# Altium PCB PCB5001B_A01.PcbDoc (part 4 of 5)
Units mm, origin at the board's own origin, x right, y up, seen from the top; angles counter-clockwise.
Board outline 115 x 60 mm, 6 copper layers (Top Layer, GND Layer 2, Signal Layer 3, Signal Layer 4, VCC Layer 5, Bottom Layer), stack 1.555 mm thick; 370 components, 274 nets, 1305 pads, 1129 vias.
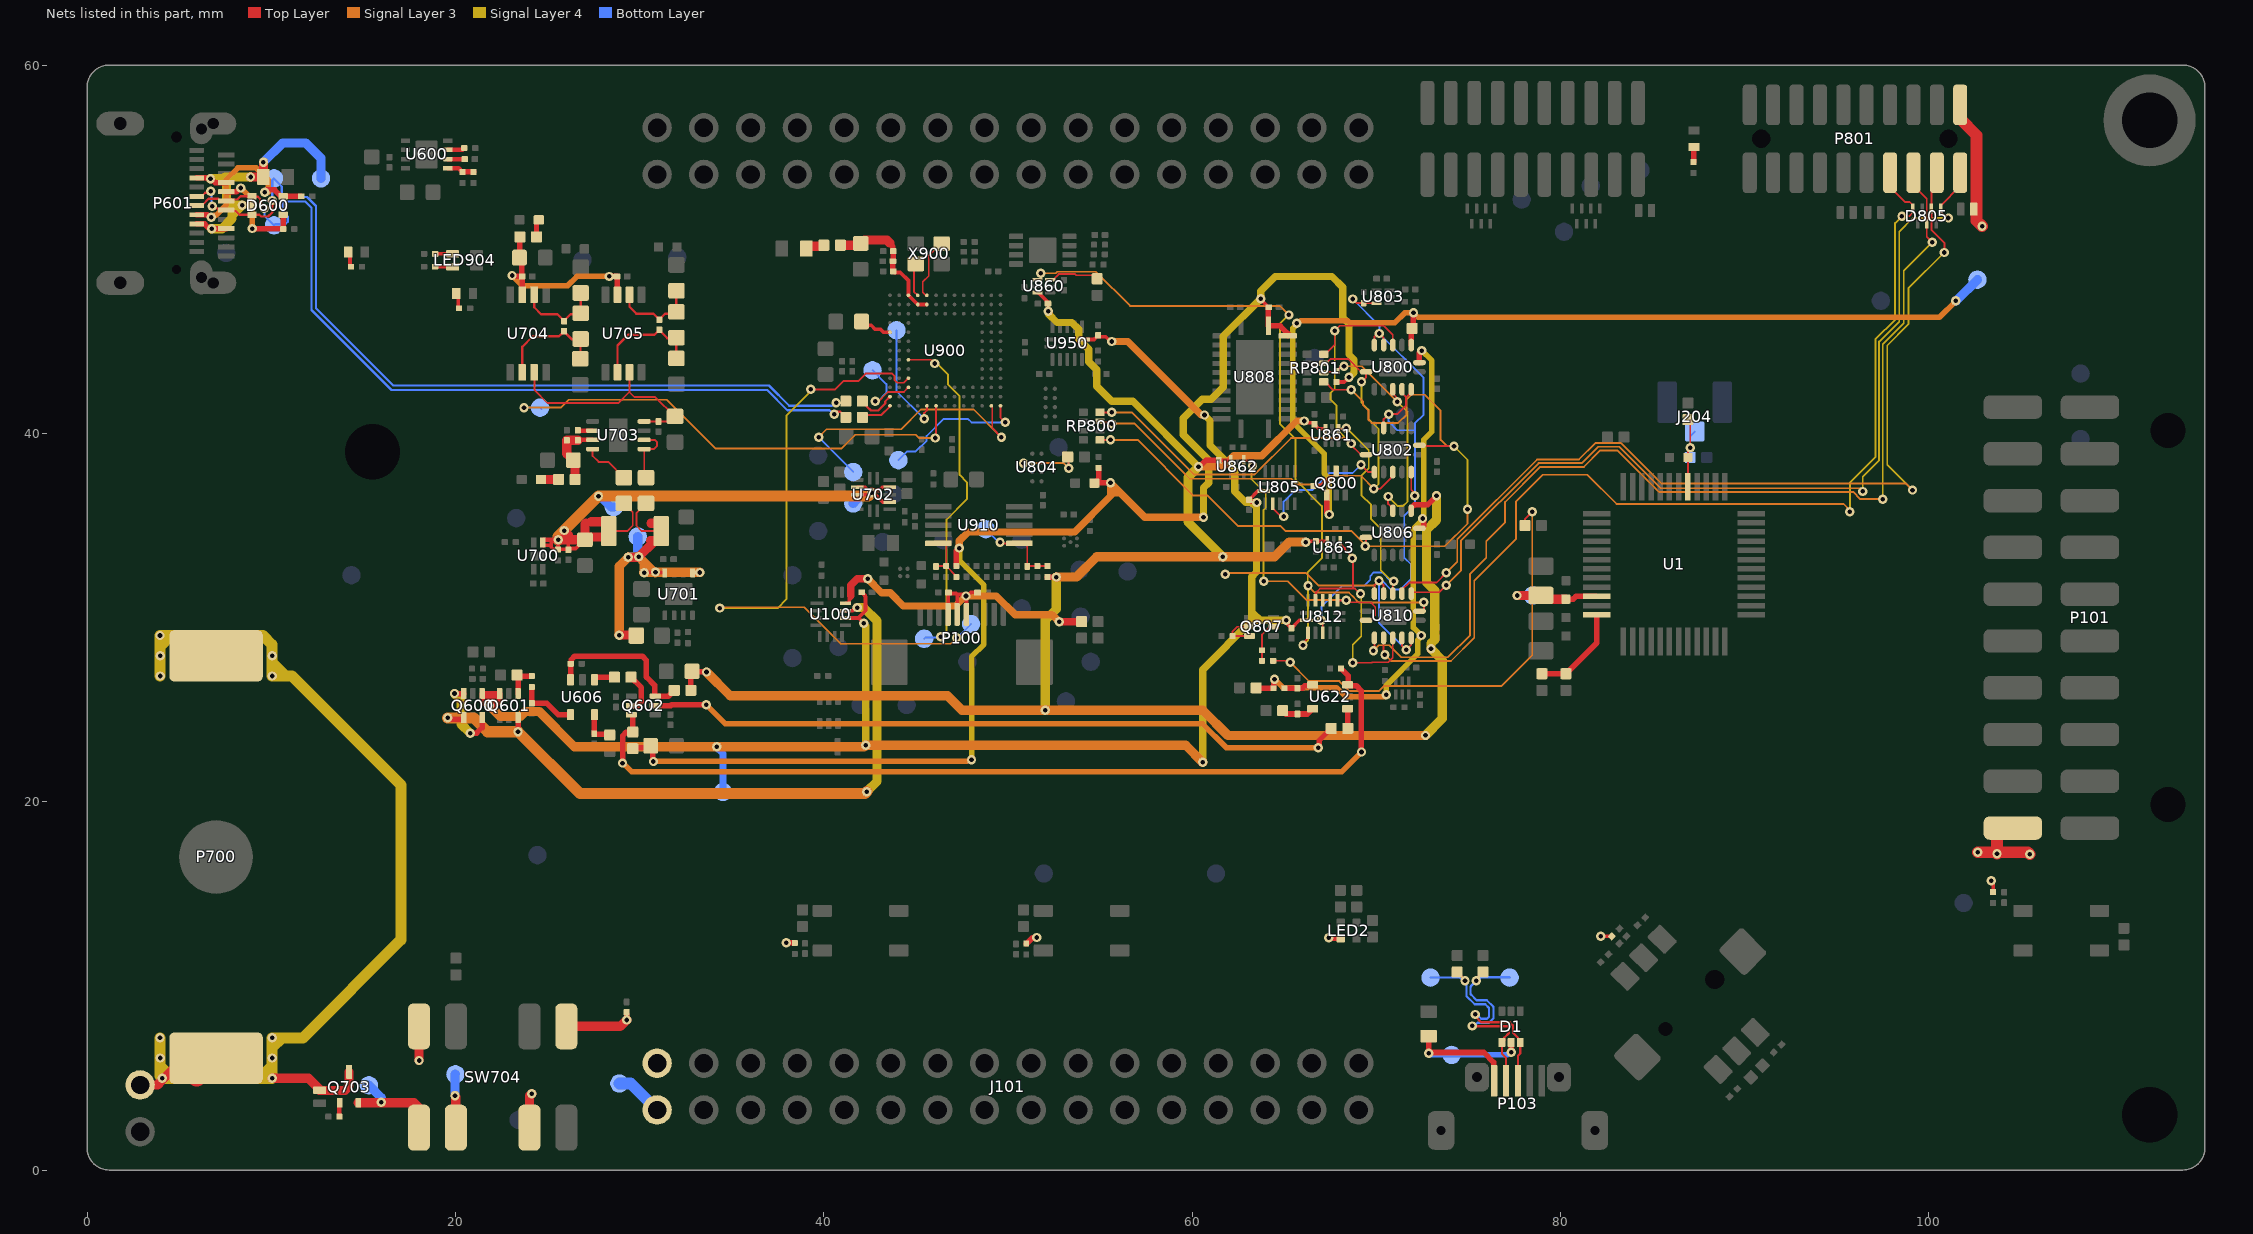
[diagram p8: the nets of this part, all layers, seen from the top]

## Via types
v1: diameter 0.508, hole 0.25, Top Layer to Bottom Layer, tented both sides, 1129 vias

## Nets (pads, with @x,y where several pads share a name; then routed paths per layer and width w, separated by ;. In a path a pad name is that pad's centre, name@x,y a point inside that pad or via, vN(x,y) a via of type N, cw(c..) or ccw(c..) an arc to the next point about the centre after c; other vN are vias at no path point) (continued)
N17581879: U802.9 U805.2 | length 7.7
  Top Layer w0.1: U805.2@64.375,36.185 64.375,35.945 v1@64.795,35.525 ; v1@69,38.3 v1(69.175,38.3) 69.575,37.9 U802.9@69.9,37.9
  Bottom Layer w0.1: v1(64.975,35.491) 64.975,36.3 65.6,36.925 66.525,36.925 67.45,37.85 68.725,37.85 v1(69.175,38.3)
N17582033: R810.1 U804.C2 | length 3.7
  Top Layer w0.1: v1(50.85,38.388) 50.863,38.4 U804.C2@51.325,38.4 ; R810.1@53.25,38.725 53.3,38.675 v1(53.3,38.1)
  Signal Layer 3 w0.1: v1(50.85,38.388) 53.038,38.388 53.325,38.1 v1(53.3,38.1)
N17582206: Q800.2 R815.1 | length 1.7
  Top Layer w0.1: R815.1@66.59,37.142 66.917,37.142 67.225,37.45 67.5,37.45 67.825,37.775 Q800.2@67.825,37.95
N17583896: Q807.5 Q807.6 R838.1 | length 2.2
  Top Layer w0.1: Q807.6@63.125,29 63.123,28.998 62.203,28.998 R838.1@62.201,28.996 62.201,29.251 62.45,29.5 Q807.5@63.125,29.5
N17584037: Q807.2 R839.2 R841.1 | length 2.2
  Top Layer w0.1: R841.1@63.804,27.652 63.802,27.654 R839.2@63.8,28.225 R839.2@63.8,28.225 63.8,29.075 64.225,29.5 Q807.2@64.425,29.5
N17584692: U810.1 U812.1 U860.4 | length 42.6
  Top Layer w0.1: U860.4@51.6,48.35 51.744,48.35 51.794,48.4 v1(51.794,48.707) ; v1(66.025,28.5) 66.025,28.625 66.3,28.9 U812.1@66.3,29.165 ; U810.1@72.35,30.35 72.375,30.375 72.55,30.375 72.6,30.425 72.599,30.808 v1(72.582,30.825)
  Signal Layer 3 w0.1: v1(51.794,48.707) 51.805,48.696 52.588,48.696 52.674,48.782 54.78,48.782 56.637,46.925 64.775,46.925 65.262,46.438 v1(65.262,46.434) ; v1(66.3,31.725) 66.668,31.357 68.524,31.357 68.807,31.074 68.807,31.062 69.037,30.832 69.049,30.832 69.056,30.825 v1(72.582,30.825)
  Signal Layer 4 w0.1: v1(65.262,46.434) 64.775,45.947 64.775,40.525 65.625,39.675 65.625,37.475 67.05,36.05 67.05,33.225 66.287,32.462 66.287,31.738 v1(66.3,31.725) 66.3,28.775 v1(66.025,28.5)
N17584702: U810.4 U812.3 U861.4 | length 17.4
  Top Layer w0.1: v1(67.025,29.85) 67.1,29.775 U812.3@67.1,29.165 ; U861.4@67.95,40.25 68.425,40.25 v1@68.45,40.275 ; U810.4@70.9,31.3 70.9,31.875 70.95,31.925 v1(70.95,31.975)
  Signal Layer 4 w0.1: v1(68.375,40.275) 68.4,40.275 69.6,39.075 69.6,38.1 69.2,37.7 69.2,36.65 69.725,36.125 69.725,35.35 70.25,34.825 70.25,32.575 70.85,31.975 v1(70.95,31.975)
  Bottom Layer w0.1: v1(67.025,29.85) 67.025,30.6 68.15,31.725 69.35,31.725 69.675,32.05 69.675,32.25 69.875,32.45 70.325,32.45 70.8,31.975 v1(70.95,31.975)
N17584725: U810.11 U812.11 U863.4 | length 13.2
  Top Layer w0.1: U812.11@66.7,30.935 66.725,30.96 66.725,31.35 66.95,31.575 68.743,31.575 ; U863.4@68.05,34.15 68.05,34.025 68.3,33.775 68.3,33.7 68.7,33.3 v1(68.7,33.225) 68.743,33.182 68.743,31.575 ; v1@68.723,27.55 69.769,27.55 69.794,27.575 70.65,27.575 70.9,27.825 U810.11@70.9,28.9 ; v1(69.15,31.3) 69.125,31.3 68.85,31.575 68.743,31.575
  Signal Layer 4 w0.1: v1(68.725,27.55) 68.725,28.525 69.193,28.993 69.193,31.218 69.15,31.261 v1(69.15,31.3)
N17584731: U810.8 U812.8 U862.4 | length 15.5
  Top Layer w0.1: U862.4@62.8,38.55 62.833,38.55 62.85,38.533 62.998,38.533 v1(63.283,38.248) ; U812.8@67.9,30.935 68.36,30.935 v1(68.375,30.95) 68.493,30.832 69.693,30.832 69.95,30.575 69.95,30.125 69.675,29.85 U810.8@69.45,29.85
  Signal Layer 3 w0.1: v1(63.9,31.975) 65.2,31.975 66.225,30.95 v1(68.375,30.95)
  Signal Layer 4 w0.1: v1(63.283,38.248) 63.225,38.189 63.225,37.525 64,36.75 64,35.95 63.875,35.825 v1@63.875,31.975
N17584764: R882.1 U860.3 | length 2.8
  Top Layer w0.1: U860.3@52.3,48.35 52.45,48.35 52.755,48.655 53.65,48.655 53.715,48.59 54.66,48.59 R882.1@54.85,48.4
N17586151: Q602.6 R674.1 R675.1 U606.3 | length 8.6
  Top Layer w0.3: U606.3@26.25,26.625 26.255,26.63 26.255,27.485 R674.1@26.26,27.49 26.27,27.49 26.28,27.5 26.28,27.707 26.474,27.9 30.15,27.9 30.375,27.675 30.375,26.773 30.825,26.323 Q602.6@30.825,25.8 ; Q602.6@30.85,25.725 31.557,25.725 R675.1@31.882,26.05
N17586225: Q602.5 R686.1 | length 38.3
  Top Layer w0.3: Q602.5@30.85,25.225 31.698,25.225 31.743,25.27 v1(33.618,25.27) ; v1(66.85,22.925) 66.897,22.972 66.897,23.323 67.5,23.926 R686.1@67.5,24.025
  Signal Layer 3 w0.3: v1(33.618,25.27) 34.663,24.225 60.575,24.225 61.868,22.932 66.161,22.932 v1@66.843,22.932
N17586229: Q602.3 R687.1 R688.1 U622.3 | length 49.2
  Top Layer w0.3: v1(29.075,22.1) 29.075,23.574 29.276,23.775 29.622,23.775 R687.1@29.629,23.783 ; Q602.3@29.55,24.725 29.625,24.725 R687.1@29.625,23.875 ; R688.1@68.086,27.233 68.096,27.233 68.475,26.854 U622.3@68.475,26.35 ; U622.3@68.375,26.375 68.441,26.309 68.916,26.309 69.2,26.025 v1(69.2,22.7)
  Signal Layer 3 w0.3: v1(29.075,22.1) 29.1,22.1 29.577,21.623 39.735,21.623 68.123,21.623 v1(69.2,22.7)
N17586339: R679.2 U606.1 | length 1.2
  Top Layer w0.3: U606.1@27.55,26.625 27.55,26.711 27.6,26.761 R679.2@28.635,26.761
N17587098: R601.1 R602.2 U600.5 | length 1.5
  Top Layer w0.25: U600.5@19.582,54.397 20.182,54.397 R601.1@20.382,54.197
  Top Layer w0.3: R601.1@20.382,54.197 R602.2@20.982,54.197
N17587122: R600.1 U600.7 | length 0.9
  Top Layer w0.25: U600.7@19.582,55.397 20.382,55.397 R600.1@20.482,55.497
N17587138: C602.1 U600.6 | length 0.9
  Top Layer w0.25: U600.6@19.582,54.897 C602.1@20.507,54.897
N17587177: Q601.4 R628.1 R672.2 | length 1.8
  Top Layer w0.3: R628.1@23.35,26.875 R628.1@23.4,26.825 ; Q601.4@23.4,25.875 R628.1@23.4,26.825 ; R672.2@24.15,26.825 R628.1@23.4,26.825
N17587185: C653.1 R629.1 U622.4 | length 1.8
  Top Layer w0.1: U622.4@66.55,26.35 U622.4@66.65,26.35
  Top Layer w0.3: R629.1@65.019,26.163 65.663,26.163 C653.1@65.7,26.2 ; C653.1@65.675,26.15 65.7,26.175 66,26.175 66.125,26.3 66.5,26.3 U622.4@66.55,26.35
N17587197: R686.2 U622.1 | length 1
  Top Layer w0.3: R686.2@68.45,24.05 68.454,24.054 68.454,25.046 U622.1@68.45,25.05
N17587207: C652.1 R690.1 U622.5 | length 1.8
  Top Layer w0.305: R690.1@64.921,24.944 65.104,24.761 C652.1@65.725,24.761 66.261,24.761 U622.5@66.55,25.05
N17587211: C660.1 R681.1 U606.5 | length 1.9
  Top Layer w0.3: U606.5@27.575,24.675 27.544,24.644 27.544,23.691 C660.1@27.537,23.685 27.537,23.665 27.547,23.655 28.38,23.655 R681.1@28.425,23.7
N17587223: Q602.2 R679.1 | length 2.2
  Top Layer w0.3: R679.1@29.535,26.761 30.1,26.196 30.1,25.426 29.899,25.225 Q602.2@29.55,25.225
N17587229: C621.1 R672.1 U606.4 | length 3.4
  Top Layer w0.3: R672.1@24.15,26.225 C621.1@24.15,25.35 24.95,25.35 25.575,24.725 U606.4@26.25,24.725 U606.4@26.25,24.85
N17587355: Q600.3 Q600.6 | length 4.3
  Top Layer w0.3: v1(19.95,25.875) Q600.6@20.45,25.875 ; v1(20.8,23.725) 21.15,23.725 21.45,24.025 Q600.3@21.45,24.575
  Signal Layer 4 w0.5: v1(19.95,25.875) 20.3,25.525 20.3,24.225 v1(20.8,23.725)
N17589135: LED903.2 R912.2 | length 0.9
  Top Layer w0.2: LED903.2@20.05,47.6 20.15,47.5 20.15,46.85 R912.2@20.2,46.8
N17589141: C903.1 C904.1 C905.1 C906.1 R130.2 U900.M9 U900.M10 U900.N11 | length 7.6
  Top Layer w0.2: C904.1@43.77,48.802 43.83,48.742 44.158,48.742 44.6,48.3 U900.N11@44.6,47.5 U900.M10@45.1,47 U900.M9@45.6,47
  Top Layer w0.3: 43.35,50.5 43.396,50.5 ; 43.573,50.323 43.75,50.146 43.75,49.906 43.76,49.896 C906.1@43.773,49.896 43.773,49.362 43.763,49.352 C905.1@43.76,49.352 43.76,48.812 43.77,48.802 C904.1@43.773,48.802
  Top Layer w0.5: R130.2@40.904,50.219 41.91,50.219 C903.1@42.006,50.315 ; C903.1@41.968,50.268 C903.1@42.075,50.375 ; C903.1@42.1,50.4 42.2,50.5 43.35,50.5 ; 43.396,50.5 43.43,50.5 43.59,50.34
N17589246: C900.1 U900.J13 | length 1.7
  Top Layer w0.2: C900.1@42.05,45.975 42.15,45.875 42.575,45.875 42.8,45.65 43.096,45.65 43.246,45.5 U900.J13@43.6,45.5
N17589624: L900.2 R130.1 | length 0.9
  Top Layer w0.5: L900.2@39.166,50.043 39.292,50.169 39.954,50.169 R130.1@40.004,50.219
N17590536: U900.N10 X900.1 | length 1.7
  Top Layer w0.1: X900.1@45,49.1 44.9,49 44.9,47.7 U900.N10@45.1,47.5
N17590538: U900.N9 X900.3 | length 3.4
  Top Layer w0.1: U900.N9@45.6,47.5 45.55,47.5 45.375,47.675 45.375,48.225 45.7,48.55 45.7,49.65 46.35,50.3 X900.3@46.4,50.3
N17590786: TPJ909.1 U900.C11 | length 4.5
  Top Layer w0.1: v1(42.8,41.75) 42.873,41.677 42.902,41.677 43.475,42.25 44.35,42.25 U900.C11@44.6,42.5
  Bottom Layer w0.1: TPJ909.1@42.651,43.427 43.4,42.679 43.4,42.2 42.95,41.75 v1(42.8,41.75) v1@42.8,41.7
N17590788: TPJ910.1 U900.D11 | length 36.8
  Top Layer w0.1: v1(39.304,42.392) 39.314,42.382 40.602,42.382 41.062,42.843 41.868,42.843 42.275,43.25 43.714,43.25 43.85,43.114 43.85,42.886 43.986,42.75 44.35,42.75 U900.D11@44.6,43
  Signal Layer 3 w0.1: v1(34.357,30.517) 34.4,30.559 38.941,30.559 40.925,28.575 46.9,28.575 v1(47.225,28.9)
  Signal Layer 4 w0.1: v1(34.357,30.517) 37.492,30.517 37.969,30.994 37.969,40.956 39.304,42.29 v1(39.304,42.392)
  Bottom Layer w0.1: v1(47.225,28.9) 47.253,28.9 TPJ910.1@48.003,29.65
N17590796: TPJ911.1 U900.F11 | length 18.7
  Top Layer w0.1: U900.F11@44.6,44 45.825,44 v1(46.025,43.8)
  Signal Layer 4 w0.1: v1(46.025,43.8) 46.125,43.8 46.75,43.175 46.75,42.65 47.375,42.025 47.375,37.75 47.775,37.35 47.775,36.425 46.675,35.325 46.675,29.255 46.388,28.968 v1(46.35,28.968)
  Bottom Layer w0.1: TPJ911.1@45.453,28.85 45.528,28.925 45.544,28.909 46.291,28.909 v1(46.35,28.968)
N17590817: TPJ900.1 U900.A2 | length 15.8
  Top Layer w0.1: U900.A2@49.1,41.5 49.15,41.45 49.15,41.314 49.15,40.3 v1(49.65,39.8)
  Signal Layer 3 w0.1: v1(39.725,39.8) 40.15,40.225 44.2,40.225 45.275,41.3 48.15,41.3 v1(49.65,39.8)
  Bottom Layer w0.1: v1(39.725,39.8) 41.602,37.923 TPJ900.1@41.602,37.9
N17590819: TPJ901.1 U900.A1 | length 7.9
  Top Layer w0.1: U900.A1@49.6,41.5 49.6,40.85 v1(49.85,40.6)
  Bottom Layer w0.1: TPJ901.1@44.053,38.55 44.528,39.025 45,39.025 45.585,39.61 45.585,39.86 46.5,40.775 47.85,40.775 48.025,40.6 v1(49.85,40.6)
N17590840: TPJ908.1 U900.A9 | length 6.2
  Top Layer w0.1: v1(45.45,40.8) 45.45,41.1 45.6,41.25 U900.A9@45.6,41.5
  Bottom Layer w0.1: TPJ908.1@43.952,45.601 43.952,42.298 v1(45.45,40.8)
N17590879: R902.2 U900.B13 | length 2.1
  Top Layer w0.12: R902.2@42.1,41.75 42.34,41.51 42.34,41.461 42.561,41.24 42.959,41.24 43.34,41.621 43.34,41.74 U900.B13@43.6,42
N17590885: R904.2 U900.A13 | length 1.8
  Top Layer w0.12: R904.2@42.1,40.875 42.225,41 43.128,41 43.585,41.456 43.585,41.485 U900.A13@43.6,41.5
N17590896: TPJ902.1 U900.A8 | length 26.7
  Top Layer w0.1: v1(46.05,39.753) 46.1,39.803 U900.A8@46.1,41.5
  Signal Layer 3 w0.1: v1(23.725,41.4) 25.725,41.4 26.15,41.825 31.484,41.825 34.134,39.175 40.95,39.175 41.7,39.925 45,39.925 45.175,39.75 46.047,39.75 v1(46.05,39.753)
  Bottom Layer w0.1: v1(23.725,41.4) TPJ902.1@24.6,41.4 TPJ902.1@24.678,41.322
N17593235: LED904.2 R920.2 | length 0.9
  Top Layer w0.2: R920.2@18.9,49.75 LED904.2@19.85,49.75
N17593237: LED904.1 R919.2 | length 0.9
  Top Layer w0.2: R919.2@18.9,49.05 LED904.1@19.85,49.05
N17593241: LED901.1 R903.2 | length 0.9
  Top Layer w0.2: LED901.1@14.175,49.85 14.275,49.75 14.275,49.1 R903.2@14.325,49.05
N17593245: LED900.1 R900.2 | length 0.8
  Top Layer w0.3: R900.2@87.235,54.74 87.242,54.748 87.242,55.542 LED900.1@87.25,55.55
N17604429: R120.1 R121.2 U1.12 | length 5.2
  Top Layer w0.305: R120.1@79,26.95 R121.2@80.3,26.95 81.975,28.625 U1.12@81.975,30.15
N17709548: SW704.2 TP704.1 | length 2.9
  Top Layer w0.508: v1(19.975,4.025) 20.025,3.975 SW704.2@20.025,2.3
  Bottom Layer w0.508: v1(19.975,4.025) 19.975,5.175 TP704.1@20,5.2
N17709572: Q703.2 SW704.1 TP156.1 | length 5.7
  Top Layer w0.508: Q703.2@14.725,3.65 17.75,3.65 18.025,3.375 SW704.1@18.025,2.3
  Bottom Layer w0.508: TP156.1@15.3,4.6 15.975,3.925 v1(15.975,3.675)
N17710582: D703.1 P700.1 Q703.3 ST701.2 | length 64.2
  Top Layer w0.5: ST701.2@2.875,4.62 3.82,4.62 v1@4.087,4.887 ; v1(4.087,4.981) v1@4.087,4.887 ; P700.1@7,6.078 5.278,6.078 v1@4.087,4.887 ; v1(10.046,4.981) 12.019,4.981 D703.1@12.675,4.325 ; D703.1@12.625,4.325 D703.1@12.675,4.325 ; Q703.3@14.225,5.325 14.225,4.55 14,4.325 D703.1@12.675,4.325
  Top Layer w1: P700.1@5.947,5.025 P700.1@7,6.078
  Signal Layer 4 w0.6: v1@3.95,27.9 v1@3.962,27.912 ; v1(3.958,7.181) 3.958,5.649 ; v1(3.962,26.825) v1@3.962,27.912 ; 3.975,5.666 3.958,5.649 ; 9.15,4.975 9.371,4.975 9.377,4.981 ; 10.05,6.65 10.581,7.181 ; 10.05,27.6 10.05,27.55 10.775,26.825 ; 3.958,5.649 4.625,4.981 ; 3.958,5.649 3.958,5.11 v1(4.087,4.981) 4.625,4.981 ; v1@3.962,27.912 v1(3.962,27.925) 3.962,28.437 ; 3.962,28.437 4.55,29.025 ; 3.962,28.437 3.962,29.019 3.958,29.023 v1(3.958,29.025) 4.55,29.025 ; 4.55,29.025 9.546,29.025 10.046,28.525 v1(10.046,27.925) v1(10.046,26.825) 10.775,26.825 ; 4.625,4.981 9.377,4.981 ; 9.377,4.981 10.046,5.65 ; 9.377,4.981 v1(10.046,4.981) 10.046,5.65 ; 10.046,5.65 v1(10.046,6.081) v1(10.046,7.181) 10.581,7.181 ; 10.581,7.181 11.714,7.181 17.039,12.506 17.039,20.919 11.133,26.825 10.775,26.825
  other v1: 3.962,6.081
N17711458: D1.6 P103.3 R118.1 TPJ403.1 | length 11.9
  Top Layer w0.12: R118.1@74.4,10.75 74.825,10.325 v1(74.825,10.275) ; v1(75.375,8.45) 75.375,8.345 75.692,8.028 77.228,8.028 77.231,8.025 77.25,8.025 77.427,7.848 77.427,7.459 77.697,7.189 77.697,7.053 D1.6@77.825,6.925 77.825,6.33 77.7,6.205 P103.3@77.7,4.85
  Bottom Layer w0.12: TPJ403.1@72.95,10.45 74.545,10.45 74.72,10.275 v1(74.825,10.275) 74.905,10.195 74.905,9.445 75.345,9.005 75.92,9.005 76.125,8.8 76.125,8.325 76.02,8.22 75.7,8.22 75.47,8.45 v1(75.375,8.45)
N17711467: D1.4 P103.2 R119.1 TPJ404.1 | length 12
  Top Layer w0.12: v1(75.225,7.825) 75.242,7.808 77.137,7.808 77.207,7.737 77.207,7.443 76.953,7.189 76.953,7.053 D1.4@76.825,6.925 76.825,6.33 77.05,6.105 P103.2@77.05,4.85 ; v1(75.433,10.275) 75.433,10.38 75.534,10.481 R119.1@75.534,10.484 ; v1@75.507,10.457 R119.1@75.534,10.484 ; R119.1@75.8,10.75 R119.1@75.534,10.484
  Bottom Layer w0.12: v1(75.225,7.825) 75.33,7.825 75.505,8 76.125,8 76.366,8.241 76.366,8.859 76.345,8.88 76.345,8.891 76.011,9.225 75.45,9.225 75.16,9.515 75.125,9.55 75.125,9.907 75.125,9.913 75.126,9.917 75.133,9.946 75.137,9.957 75.152,9.994 v1(75.433,10.275) 75.507,10.275 75.697,10.465 77.232,10.465 TPJ404.1@77.247,10.45
N17711475: D1.5 L1.1 P103.1 TPJ405.1 | length 10.8
  Top Layer w0.305: L1.1@72.85,7.27 v1(72.85,6.35) 72.88,6.38 75.845,6.38 76.378,5.847 76.378,5.547 76.4,5.525 P103.1@76.4,4.85 ; v1(77.325,6.4) D1.5@77.325,6.925
  Bottom Layer w0.305: v1(72.85,6.35) 72.948,6.252 TPJ405.1@74.098,6.252 77.122,6.252 77.27,6.4 v1(77.325,6.4)
N17935558: C729.1 R718.2 U703.4 U704.3 U705.3 | length 12.6
  Top Layer w0.1: U704.3@24.275,43.32 24.302,43.293 24.302,42.784 24.302,42.348 25,41.65 28.85,41.65 29.45,42.25 ; U705.3@29.45,43.32 29.45,42.25 ; U703.4@30.25,40.65 C729.1@31.025,40.65 31.028,40.653 31.653,40.653 R718.2@31.925,40.925 ; R718.2@31.95,40.925 R718.2@31.925,40.925 ; 29.45,42.25 29.725,41.975 30.85,41.975 31.9,40.925 R718.2@31.925,40.925
N17935560: C766.2 R765.2 R767.2 U704.2 | length 6.2
  Top Layer w0.127: U704.2@23.625,43.32 23.625,44.7 24.2,45.275 25.625,45.275 25.783,45.434 25.803,45.434 C766.2@25.9,45.53 ; R767.2@26.775,44.05 26.788,44.063 R765.2@26.788,45.113 ; R765.2@26.8,45.125 R765.2@26.788,45.113 ; C766.2@25.9,45.53 C766.2@25.9,45.55 C766.2@25.9,45.53 ; C766.2@25.9,45.53 26.325,45.105 26.78,45.105 R765.2@26.788,45.113
N17935562: C766.1 R764.1 R765.1 U704.6 | length 4.8
  Top Layer w0.127: U704.6@24.275,47.531 24.275,46.85 24.65,46.475 25.545,46.475 C766.1@25.9,46.12 ; C766.1@25.9,46.1 C766.1@25.9,46.12 ; R764.1@26.8,47.625 R765.1@26.8,46.525 26.75,46.475 26.255,46.475 C766.1@25.9,46.12
N17935584: L704.2 R731.2 | length 1
  Top Layer w0.254: R731.2@24.4,50.675 24.4,51.477 24.523,51.6 L704.2@24.525,51.6
N17935601: C730.1 C731.1 C732.1 R731.1 U704.7 U705.7 | length 10.9
  Top Layer w0.305: v1(23.075,48.575) 23.117,48.533 C730.1@23.597,48.533 ; R731.1@23.5,50.675 23.488,50.662 23.488,49.563 C731.1@23.475,49.55 23.597,49.428 C730.1@23.597,48.533 ; U704.7@23.625,47.531 C730.1@23.625,48.525 23.605,48.525 C730.1@23.597,48.533 ; v1(28.35,48.525) C732.1@28.775,48.525 C732.1@28.78,48.525 ; U705.7@28.775,47.556 U705.7@28.787,47.543 ; C732.1@28.792,48.525 C732.1@28.78,48.525 ; U705.7@28.8,47.531 U705.7@28.787,47.543 ; C732.1@28.78,48.525 28.787,48.517 U705.7@28.787,47.543
  Signal Layer 3 w0.305: v1(23.075,48.575) 23.62,48.03 26.097,48.03 26.593,48.525 v1(28.35,48.525)
N17935617: C770.2 R769.2 R771.2 U705.2 | length 6.4
  Top Layer w0.127: U705.2@28.8,43.32 28.8,44.775 29.375,45.35 30.8,45.35 30.959,45.508 30.979,45.508 C770.2@31.075,45.605 ; R771.2@32,44.075 R769.2@32,45.2 31.975,45.175 31.505,45.175 C770.2@31.075,45.605 ; C770.2@31.075,45.605 C770.2@31.075,45.625 C770.2@31.075,45.605
N17935627: C770.1 R768.1 R769.1 U705.6 | length 4.8
  Top Layer w0.127: U705.6@29.45,47.531 29.45,46.875 29.825,46.5 30.75,46.5 30.959,46.291 30.979,46.291 C770.1@31.075,46.195 ; C770.1@31.075,46.175 C770.1@31.075,46.195 ; R768.1@32,47.75 R769.1@32,46.6 31.9,46.5 31.38,46.5 C770.1@31.075,46.195
N17935973: R709.1 U703.1 U703.2 | length 3.3
  Top Layer w0.1: U703.2@30.25,39.65 30.825,39.65 30.95,39.525 30.95,39.325 30.775,39.15 U703.1@30.25,39.15 30.25,37.7 R709.1@30.35,37.6
N17935989: C710.2 U703.6 | length 0.8
  Top Layer w0.25: C710.2@26.65,40.175 26.675,40.15 U703.6@27.45,40.15
N17936021: R710.1 U703.8 | length 2.6
  Top Layer w0.1: U703.8@27.45,39.15 27.45,38.775 27.775,38.45 28.3,38.45 R710.1@29.15,37.6
N17936029: L700.2 R717.1 | length 1
  Top Layer w0.5: L700.2@24.65,37.5 R717.1@25.6,37.5
N175081141: Q703.1 R792.2 | length 0.8
  Top Layer w0.254: R792.2@13.7,2.9 13.7,3.625 Q703.1@13.725,3.65
SI_HEADER_ENABLE: R807.1 U800.5 U800.6 U800.12 U800.13 U802.5 U802.13 U803.3 U810.5 U810.6 U810.12 U810.13 | length 45.6
  Top Layer w0.1: v1(68.725,47.3) 68.95,47.075 R807.1@69.325,47.075 U803.3@70.025,47.075 ; U810.6@69.9,31.3 69.9,31.75 v1(70.15,32) 70.4,31.75 U810.5@70.4,31.3 ; U800.6@69.9,44.8 69.9,45.25 70.075,45.425 v1(70.175,45.425) 70.4,45.2 U800.5@70.4,44.8 ; U802.5@70.4,40.3 70.4,40.775 v1(70.675,41.05) 71.15,41.05 71.625,41.525 71.625,41.975 ; U810.12@71.4,28.9 71.4,28.475 v1(71.625,28.25) 71.9,28.525 U810.13@71.9,28.9 ; U800.12@71.4,42.4 71.4,42.2 71.625,41.975 ; U800.13@71.875,42.45 U800.13@71.925,42.4 ; U802.13@71.9,37.9 71.9,36.935 72.075,36.76 v1@72.075,36.625 ; U800.13@71.9,42.4 71.9,42.25 71.625,41.975
  Signal Layer 3 w0.1: v1@61.85,32.425 66.175,32.425 66.85,31.75 69.9,31.75 v1(70.15,32)
  Bottom Layer w0.1: v1(68.725,47.3) 70.175,45.85 v1(70.175,45.425) 72.575,43.025 72.575,41.025 72.1,40.55 72.1,40.175 ; v1(70.675,41.05) 70.675,40.65 71.15,40.175 72.1,40.175 ; v1(71.625,28.25) 70.15,29.725 v1(70.15,32) 70.325,32 70.8,31.525 71.3,31.525 71.893,32.118 71.893,32.882 71.525,33.25 71.525,35.525 72.1,36.1 v1(72.1,36.625) 72.1,40.175
  other v1: 61.8,32.35
SI_VCOM_CTS: D805.4 P801.8 U810.10 | length 55.1
  Top Layer w0.1: U810.10@70.4,28.9 70.4,28.05 v1(70.475,27.975) ; P801.8@97.905,54.158 97.905,53.37 98.7,52.575 98.96,52.575 99.15,52.385 D805.4@99.15,52.215 99.15,52 98.95,51.8 v1(98.55,51.8)
  Signal Layer 3 w0.1: v1(70.475,27.975) 70.807,27.643 74.062,27.643 75.325,28.906 75.325,32.008 77.6,34.283 77.6,36.309 79.048,37.757 81.468,37.757 83.05,36.175 95.375,36.175 95.725,35.825 v1(95.725,35.75)
  Signal Layer 4 w0.1: v1(95.725,35.75) 95.725,37.325 97.111,38.711 97.111,45.111 98.175,46.175 98.175,51.425 v1(98.55,51.8)
SI_VCOM_RTS: D805.6 P801.6 U810.9 | length 56.9
  Top Layer w0.1: v1(69.85,28.2) 69.9,28.25 U810.9@69.9,28.9 ; P801.6@99.175,54.158 99.175,53.475 99.9,52.75 D805.6@99.9,51.385 99.9,50.675 v1(100.2,50.375)
  Signal Layer 3 w0.1: v1(69.85,28.2) 70.15,28.5 70.7,28.5 71.357,27.843 73.893,27.843 75.1,29.05 75.1,32.369 75.975,33.244 75.975,34.144 77,35.169 77,36.275 78.91,38.185 81.285,38.185 82.175,39.075 83.1,39.075 85.35,36.825 95.894,36.825 96.286,36.434 v1(97.511,36.434)
  Signal Layer 4 w0.1: v1(97.511,36.434) 97.511,44.836 98.65,45.975 98.65,48.825 v1(100.2,50.375)
SI_VCOM_RXD: D805.1 P801.2 U810.2 | length 50.8
  Top Layer w0.1: U810.2@71.9,31.3 71.9,31.375 73.425,31.375 v1(73.8,31.75) ; v1(101.075,51.7) 101,51.7 100.65,52.05 D805.1@100.65,52.215 100.65,52.375 101.715,53.44 P801.2@101.715,54.158
  Signal Layer 3 w0.1: v1(73.8,31.75) 74.6,32.55 74.6,34.167 78.818,38.385 81.16,38.385 82.05,39.275 83.2,39.275 85.45,37.025 96.25,37.025 v1(96.425,36.85)
  Signal Layer 4 w0.1: v1(96.425,36.85) 96.425,37.65 97.311,38.536 97.311,44.986 98.4,46.075 98.4,50.95 99.15,51.7 v1(101.075,51.7)
SI_VCOM_TXD: D805.2 P801.4 U810.3 | length 52.5
  Top Layer w0.1: U810.3@71.4,31.3 71.4,31.5 71.8,31.9 73.275,31.9 v1(73.8,32.425) ; P801.4@100.445,54.158 100.15,53.863 D805.2@100.15,52.215 100.15,51.05 100.869,50.331 100.869,49.844 v1(100.85,49.825)
  Signal Layer 3 w0.1: v1(73.8,32.425) 74.4,33.025 74.4,34.25 78.735,38.585 81.01,38.585 81.9,39.475 83.3,39.475 85.5,37.275 98.775,37.275 v1(99.125,36.925)
  Signal Layer 4 w0.1: v1(99.125,36.925) 97.75,38.3 97.75,44.775 98.9,45.925 98.9,47.875 v1(100.85,49.825)
TCK_SWCLK: RP800.3 RP801.3 U800.8 U802.11 | length 28.6
  Top Layer w0.1: RP800.3@55,40.65 55.058,40.592 55.575,40.592 v1(55.633,40.534) ; RP801.3@67.15,43.8 67.289,43.8 67.539,44.05 68.475,44.05 69.175,43.35 U800.8@69.45,43.35 69.45,43.05 v1@69.203,42.803 ; v1(69.875,37) 70.224,37 70.9,37.676 U802.11@70.9,37.9
  Signal Layer 3 w0.1: v1(55.633,40.534) 56.891,40.534 59.887,37.538 62.488,37.538 65.387,37.538 65.7,37.225 67,37.225 67.475,37.7 69.175,37.7 v1(69.875,37)
  Signal Layer 4 w0.1: 69.203,42.35 69.203,41.672 ; v1(69.203,42.802) 69.203,41.672 ; v1(69.875,37) 70.125,37.25 70.125,40.25 69.575,40.8 69.575,41.3 69.203,41.672
TDI: RP800.1 RP801.1 U802.1 U806.8 | length 41.3
  Top Layer w0.1: RP800.1@55,39.65 v1(55.575,39.65) ; RP801.1@67.15,42.8 67.227,42.8 67.652,42.375 v1(68.65,42.375) ; v1@69.45,33.975 U806.8@69.45,34.35 ; U802.1@72.35,39.35 72.374,39.326 74.202,39.326 v1(74.226,39.302)
  Signal Layer 3 w0.1: v1(55.575,39.65) 57.05,39.65 60.075,36.625 60.85,36.625 62.507,34.968 64.807,34.968 65.068,34.707 68.643,34.707 69.4,33.95 v1(69.4,33.875) 73.725,33.875 74.957,35.107 v1(74.957,35.875) ; v1(68.65,42.375) 69.275,41.75 69.275,41.55 69.575,41.25 69.575,40.75 69.75,40.575 71.2,40.575 71.65,41.025 71.65,41.85 71.9,42.1 72.625,42.1 73.5,41.225 73.5,39.65 73.822,39.328 74.147,39.328 v1@74.2,39.275
  Signal Layer 4 w0.1: v1(74.226,39.302) 74.957,38.571 v1(74.957,35.875)
TDO_SWO: R801.1 RP801.2 U800.11 U806.4 | length 13.7
  Top Layer w0.1: RP801.2@67.15,43.3 67.196,43.346 67.803,43.346 R801.1@67.849,43.393 67.849,43.403 68.018,43.572 68.172,43.572 v1@68.225,43.625 ; v1@68.175,43.625 v1@68.225,43.625 ; v1(68.25,43.65) v1@68.225,43.625 ; v1(70.65,36.575) 70.65,36.174 70.9,35.924 U806.4@70.9,35.8 ; U800.11@70.9,42.4 70.9,42.175 71.15,41.925 v1(71.15,41.725)
  Signal Layer 3 w0.1: v1(68.25,43.65) 69.225,43.65 v1(71.15,41.725)
  Signal Layer 4 w0.1: v1(70.65,36.575) 70.65,36.569 71.169,36.05 71.45,36.05 71.7,36.3 71.7,41.175 v1(71.15,41.725)
TMS_SWDIO: RP800.4 RP801.4 U800.4 U802.8 | length 29.5
  Top Layer w0.1: RP800.4@55,41.15 55.008,41.142 v1(55.646,41.142) ; RP801.4@67.15,44.3 67.225,44.3 67.75,44.825 v1(67.75,45.575) 68.025,45.85 70.4,45.85 70.9,45.35 U800.4@70.9,44.8 ; v1(68.65,39.45) 68.575,39.45 69.175,38.85 U802.8@69.45,38.85
  Signal Layer 3 w0.1: v1(55.646,41.142) 56.733,41.142 60.1,37.775 63.4,37.775 65.375,39.75 68.3,39.75 68.6,39.45 v1(68.65,39.45)
  Signal Layer 4 w0.1: v1(67.75,45.575) 67.75,42.425 67.525,42.2 67.525,41.825 67.85,41.5 67.85,40.225 68.625,39.45 v1(68.65,39.45)
UFL_ADC_IN: C113.1 J204.1 R5.2 R220.2 U1.41 | length 5.3
  Top Layer w0.1: U1.41@86.925,37.1 C113.1@86.925,38.7 86.925,39.1 v1(87.05,39.225) 87.05,40.625 R5.2@86.925,40.75
  Bottom Layer w0.1: R220.2@87.05,38.7 v1(87.05,39.225) 87.05,39.85 J204.1@87.3,40.1
USB_DM: D600.6 P601.A7 P601.B7 R902.1 TPJ612.1 | length 46.9
  Top Layer w0.12: P601.B7@5.95,52.875 6.215,52.875 6.409,53.069 6.639,53.069 v1(6.713,53.143) ; v1(6.788,52.337) 6.862,52.263 7.012,52.263 7.075,52.2 7.475,52.2 7.604,52.071 8.079,52.071 8.276,51.874 9.351,51.874 9.45,51.775 9.825,51.775 10.05,52 v1(10.05,52.651) ; v1(40.669,41.657) 41.107,41.657 R902.1@41.2,41.75
  Bottom Layer w0.12: v1(6.713,53.143) 6.75,53.106 6.75,52.375 v1(6.788,52.337) ; v1@10.049,52.66 10.05,52.659 v1(10.05,52.651) ; v1@10.05,52.661 10.05,53.75 TPJ612.1@10.15,53.85 10.15,53.826 10.569,53.407 10.569,53.031 10.76,52.84 11.935,52.84 12.425,52.35 12.425,46.8 16.625,42.6 37.025,42.6 38.125,41.5 40.431,41.5 40.588,41.657 v1(40.669,41.657)
USB_DP: D600.4 P601.A6 P601.B6 R904.1 TPJ611.1 | length 46.4
  Top Layer w0.12: P601.B6@5.95,52.375 6.025,52.45 6.3,52.45 6.59,52.74 7.12,52.74 7.235,52.625 P601.A6@7.55,52.625 7.625,52.7 8.155,52.7 8.329,52.874 D600.4@8.947,52.874 8.97,52.85 9.275,52.85 9.381,52.744 9.381,52.574 9.625,52.33 9.625,52.225 v1(9.621,52.221) ; v1(40.578,41.047) 40.704,41.173 40.898,41.173 40.9,41.175 R904.1@41.2,40.875
  Bottom Layer w0.12: v1(9.621,52.221) 9.625,52.221 9.625,51.825 TPJ611.1@10.15,51.3 10.21,51.36 10.76,51.36 10.9,51.5 10.9,51.78 10.605,52.075 10.605,52.53 10.675,52.6 11.836,52.6 12.185,52.251 12.185,46.701 16.526,42.36 36.926,42.36 38.026,41.26 40.315,41.26 40.528,41.047 v1(40.578,41.047)
USBC_CC1: D600.1 P601.A5 R621.2 | length 5.9
  Top Layer w0.3: P601.A5@7.55,53.125 8.1,53.125 8.3,53.325 v1(8.35,53.325) ; v1(8.975,51.125) 8.99,51.11 10.64,51.11 R621.2@10.648,51.102 ; R621.2@10.65,51.1 R621.2@10.648,51.102 ; D600.1@10.675,51.875 10.648,51.848 R621.2@10.648,51.102
  Signal Layer 3 w0.3: v1(8.35,53.325) 8.975,52.7 v1(8.975,51.125) v1@8.975,51.05
USBC_CC2: D600.3 P601.B5 R620.2 | length 9.1
  Top Layer w0.3: P601.B5@5.95,51.875 6.525,51.875 6.667,51.733 v1(6.746,51.731) v1(6.746,51.731) ; v1(9.64,53.103) 9.761,53.224 10.183,53.224 10.533,52.874 11.599,52.874 R620.2@11.6,52.875
  Signal Layer 3 w0.3: v1(6.746,51.731) v1(6.746,51.731) 6.779,51.733 6.891,51.844 6.992,51.844 7.55,52.403 7.55,53.786 8.182,54.418 9.173,54.418 9.825,53.765 9.825,53.103 v1(9.64,53.103)
USBC_VBUS: D600.5 L600.1 P601.A4 P601.A9 P601.B4 P601.B9 TPJ613.1 | length 18.1
  Top Layer w0.3: P601.B4@5.95,51.375 6.384,51.375 6.594,51.165 6.76,51.165 6.762,51.163 v1(6.762,51.119) 6.768,51.125 P601.A9@7.55,51.125 ; P601.B9@5.95,53.875 6.475,53.875 6.485,53.865 6.66,53.865 v1(6.7,53.825) ; v1@6.675,53.825 v1(6.7,53.825) ; P601.A4@7.55,53.625 6.956,53.625 6.756,53.825 v1(6.7,53.825) ; v1(8.425,52.4) 8.438,52.387 8.934,52.387 D600.5@8.947,52.374
  Top Layer w0.5: v1@8.876,53.926 L600.1@9.57,53.926 ; L600.1@9.57,53.926 9.573,53.93 v1(9.575,54.725) v1(9.575,54.725)
  Signal Layer 4 w0.5: v1(6.7,53.825) 7.382,53.825 ; v1(6.762,51.119) 7.319,51.119 7.868,51.668 7.868,52.4 ; 7.868,51.843 v1(8.425,52.4) ; v1@8.35,52.4 7.868,52.4 ; v1(8.875,53.925) 7.868,53.925 ; 7.382,53.825 7.482,53.925 7.868,53.925 ; 7.382,53.825 7.575,53.632 ; 7.575,53.632 7.575,52.693 7.868,52.4 ; 7.575,53.632 7.868,53.925
  Bottom Layer w0.5: v1@9.6,54.75 10.625,55.775 11.875,55.775 12.7,54.95 TPJ613.1@12.7,53.85
V_SW: C104.1 C800.1 C828.1 C950.1 Q600.4 Q601.6 TPJ608.1 U100.10 U805.14 U812.14 U950.14 | length 93
  Top Layer w0.2: U100.10@41.19,29.975 41.9,29.975 v1(42.175,29.7) ; 41.87,29.975 42.27,30.376 42.27,31.127 42.243,31.154 42.243,31.197 42.153,31.287 42.153,31.314 42.093,31.374 C104.1@42.073,31.374 ; U950.14@54.11,45.1 54.675,45.1 54.82,45.245 54.84,45.245 54.9,45.305 C950.1@54.9,45.325 54.946,45.279 54.946,45.259 54.96,45.245 55.311,45.245 55.562,44.994 v1(55.646,44.994) ; v1(63.521,36.25) 63.55,36.25 63.525,36.275 63.225,36.275 C800.1@63.1,36.4 63.57,36.87 U805.14@63.89,36.87 ; v1(65.125,29.85) 65.125,29.7 C828.1@65.4,29.425 65.825,29.85 U812.14@66.215,29.85
  Top Layer w0.3: 21.45,25.475 22.282,25.475 22.341,25.416 ; 21.45,25.475 Q600.4@21.45,25.625 ; 21.45,25.475 21.7,25.225 v1(21.85,25.225) 22.15,25.225 22.341,25.416 ; Q600.4@21.45,25.625 Q601.6@22.4,25.625 ; Q600.4@21.45,25.625 Q600.4@21.45,25.875 Q601.6@22.4,25.875 Q601.6@22.4,25.625 ; 22.341,25.416 22.4,25.475 Q601.6@22.4,25.625
  Signal Layer 3 w0.4: v1(55.646,44.994) 56.506,44.994 60.5,41 v1(60.675,41)
  Signal Layer 3 w0.5: v1(21.85,25.225) 22.45,24.625 23.525,24.625 23.8,24.9 24.55,24.9 26.459,22.991 v1(34.183,22.991) 41.02,22.991 42.2,22.991 v1(42.274,23.065) 59.66,23.065
  Signal Layer 3 w0.508: 59.66,23.065 v1(60.575,22.15)
  Signal Layer 4 w0.4: v1(42.175,29.7) 42.175,29.671 42.274,29.572 v1(42.274,23.065) ; v1(60.575,22.15) 60.575,27.175 63.25,29.85 ; v1(60.675,41) 60.975,40.7 60.975,39.35 62.325,38 62.325,36.85 62.925,36.25 63.225,36.25 ; 63.325,30.225 63.7,29.85 ; v1(65.125,29.85) 63.7,29.85 ; 63.225,36.25 63.5,35.975 ; 63.225,36.25 v1(63.521,36.25) 63.5,36.229 63.5,35.975 ; 63.25,29.85 63.25,30.225 63.25,32.225 63.5,32.475 63.5,35.975 ; 63.25,29.85 63.7,29.85
  Bottom Layer w0.4: v1(34.183,22.991) 34.183,22.962 34.528,22.616 TPJ608.1@34.528,20.527
VCOM_CTS: U812.9
VCOM_ENABLE: R300.2 R841.2 | length 24.3
  Top Layer w0.1: R841.2@64.404,27.652 65.248,27.652 v1(65.325,27.575) ; R300.2@78.075,35 78.075,35.344 v1(78.478,35.747)
  Signal Layer 3 w0.1: v1(65.325,27.575) 66.35,26.55 68,26.55 68.543,26.007 70.146,26.007 70.431,26.292 76.817,26.292 78.475,27.95 78.475,33.11 78.475,35.744 v1(78.478,35.747)
VCOM_RTS: U812.10
VCS: C710.1 C714.1 C728.1 R717.2 U703.7 | length 3.7
  Top Layer w0.25: C710.1@26.675,39.65 U703.7@27.45,39.65
  Top Layer w0.3: C710.1@26.65,39.625 C710.1@26.675,39.65
  Top Layer w0.5: R717.2@26.5,37.5 26.5,38.45 C714.1@26.4,38.55 26.05,38.9 C728.1@26.05,39.625 C710.1@26.65,39.625
VDISP: C143.1 C144.1 P100.4 P100.5 P100.6 R145.2 U100.12 | length 20.6
  Top Layer w0.2: U100.12@41.19,30.775 41.39,30.775 41.39,30.975 ; 41.4,31.25 41.39,31.24 41.39,30.975 ; 41.45,31.1 41.45,31.035 41.39,30.975 ; P100.4@46.75,30.175 46.762,30.187 46.762,31.352 C143.1@46.774,31.364 46.834,31.304 47.196,31.304 47.25,31.25 ; P100.5@47.25,30.175 47.25,31.25 ; P100.6@47.75,30.175 v1@47.75,31.174 ; v1@47.75,31.175 47.725,31.2 v1@47.815,31.2 ; C144.1@48.35,31.368 47.984,31.368 v1@47.815,31.2 ; 47.25,31.25 47.575,31.25 47.65,31.174 v1(47.724,31.174) v1@47.75,31.174 ; v1@47.75,31.174 47.79,31.174 v1@47.815,31.2
  Top Layer w0.4: 41.475,31.175 41.475,31.75 41.825,32.1 v1(42.384,32.1) ; R145.2@54.007,29.782 R145.2@54.007,29.782 v1@52.784,29.781 ; v1(52.783,29.781) v1@52.784,29.781
  Signal Layer 3 w0.4: v1(42.384,32.1) 43.137,31.347 43.61,31.347 44.325,30.632 47.153,30.632 47.695,31.174 49.368,31.174 50.396,30.146 52.418,30.146 v1@52.763,29.801
VMCU: C1.1 C2.1 C706.1 D808.1 J101.1 J101.2 LED2.1 P101.2 P801.1 Q600.1 Q601.3 R9.1 R100.2 R101.2 R111.2 SW704.3 SW704.5 SW704.8 TP157.1 TP703.1 U1.10 U100.11 | length 68.4
  Top Layer w0.2: U100.11@41.19,30.375 41.56,30.375 41.729,30.544 v1(41.812,30.544) ; v1(82.2,12.7) 82.212,12.688 R111.2@82.788,12.688 ; v1(103.4,15.7) 103.5,15.6 R9.1@103.5,15.1
  Top Layer w0.3: v1(19.577,24.551) 19.577,24.548 19.65,24.475 20.35,24.475 Q600.1@20.45,24.575 ; v1(23.4,23.8) Q601.3@23.4,24.575 ; v1@37.9,12.325 37.917,12.342 38.421,12.342 R101.2@38.429,12.333 ; R100.2@51,12.3 51.025,12.3 51.35,12.625 v1(51.575,12.625) ; v1(67.425,12.618) 67.446,12.596 68.054,12.596 LED2.1@68.075,12.575
  Top Layer w0.305: v1(29.3,8.15) C706.1@29.3,8.475 ; C2.1@80.3,31 80.7,31 80.85,31.15 U1.10@81.927,31.15
  Top Layer w0.508: v1(18.025,5.95) SW704.5@18.025,7.8 ; SW704.3@24.025,2.3 24.025,4.025 v1(24.15,4.15) ; SW704.8@26.025,7.8 28.95,7.8 v1(29.3,8.15) ; v1(77.65,31.2) 78.75,31.2 78.95,31 C2.1@80.3,31
  Top Layer w0.635: P801.1@101.715,57.841 101.715,57.085 102.6,56.2 ; 102.598,56.173 102.598,51.546 v1(102.9,51.244) ; v1(102.67,17.264) 105.389,17.264 v1(105.498,17.155) ; v1(103.709,17.184) 103.709,18.253 104.027,18.57 P101.2@104.57,18.57
  Signal Layer 3 w0.6: v1(19.577,24.551) 20.999,24.551 21.75,23.8 v1(23.4,23.8) 26.758,20.442 42.232,20.442 v1(42.341,20.552)
  Signal Layer 4 w0.3: v1(19.577,24.551) v1@19.625,24.503
  Signal Layer 4 w0.5: v1(41.812,30.544) 41.814,30.542 42.171,30.542 42.9,29.813 42.9,21.112 42.341,20.554 v1(42.341,20.552)
  Bottom Layer w0.508: v1(77.65,31.2) TP157.1@78.5,31.2
  Bottom Layer w0.635: TP703.1@28.9,4.7 29.512,4.7 J101.1@30.95,3.262
  other v1: 37.968,12.35
VMCU_BUF: C625.1 C861.1 C863.1 C865.1 C867.1 R630.2 R675.2 U806.2 U860.6 U861.6 U862.6 U863.6 | length 112
  Top Layer w0.2: U860.6@51.6,47.65 51.65,47.65 52.175,47.125 C863.1@52.175,47.05 52.188,47.037 52.188,46.655 v1(52.201,46.642) ; C861.1@61.45,38.55 U862.6@62.1,38.55 ; v1(66.099,40.674) 66.182,40.674 66.275,40.58 66.59,40.58 66.65,40.52 66.65,40.48 66.88,40.25 U861.6@67.25,40.25 ; v1(66.175,34.1) 66.225,34.15 C867.1@66.725,34.15 U863.6@67.35,34.15
  Top Layer w0.3: R675.2@32.782,26.05 32.782,27.015 C625.1@32.848,27.08 32.866,27.063 33.618,27.063 v1(33.635,27.046) ; R630.2@52.15,32.2 v1(52.625,32.2) ; v1(60.354,38.189) 60.41,38.189 60.771,38.55 C861.1@61.45,38.55 ; U806.2@71.9,35.8 71.9,35.95 72.075,36.125 72.79,36.125 73.275,36.61 v1(73.275,36.625)
  Signal Layer 3 w0.4: v1(60.354,38.189) 61.664,38.189 62.265,38.79 63.79,38.79 65.674,40.674 v1(66.099,40.674)
  Signal Layer 3 w0.5: v1(33.635,27.046) 34.924,25.757 46.718,25.757 47.512,24.963 v1@52.013,24.963 ; v1(52.025,24.975) v1@52.013,24.963 ; v1(52.625,32.2) 53.729,32.2 54.829,33.3 v1(61.675,33.3) 64.475,33.3 65.275,34.1 v1(66.175,34.1) ; v1(72.675,23.6) 61.95,23.6 60.587,24.963 v1@52.013,24.963
  Signal Layer 4 w0.4: v1(52.201,46.642) 52.221,46.621 52.221,46.474 52.67,46.025 53.475,46.025 53.85,45.65 53.85,45.123 54.4,44.573 54.4,43.889 54.825,43.464 54.825,42.559 55.634,41.75 56.793,41.75 60.318,38.225 60.318,38.204 v1@60.304,38.189
  Signal Layer 4 w0.5: v1(52.025,24.975) 52.025,29.861 52.625,30.461 v1(52.625,32.2) ; v1(60.354,38.189) 60.354,38.187 59.775,37.609 59.775,35.2 v1(61.675,33.3) ; v1(72.675,23.6) 73.591,24.516 73.591,27.684 v1(72.975,28.3) v1(72.975,28.3) 72.977,28.602 73.175,28.8 73.175,31.472 72.725,31.922 72.725,34.75 73.275,35.3 v1(73.275,36.625)
VMCU_R: R701.1 R702.2 R709.2 TP700.1 U701.1 U701.4 | length 21
  Top Layer w0.1: R709.2@30.35,36.2 29.825,35.675 29.825,35 30.125,34.7 R701.1@31.175,34.7
  Top Layer w0.2: v1(30.258,32.443) 30.273,32.457 30.851,32.457 v1(30.865,32.471) 30.888,32.448 31.352,32.448 U701.4@31.375,32.425 ; U701.1@32.875,32.425 32.887,32.437 33.262,32.437 v1(33.275,32.45)
  Top Layer w0.5: v1(28.9,29.05) 28.902,29.048 29.788,29.048 R702.2@29.816,29.021 ; v1(29.39,33.276) 29.391,33.278 29.935,33.278 v1(29.962,33.302) v1(29.962,33.302) ; v1@29.963,33.304 30.784,34.125 31,34.125 31.175,34.3 R701.1@31.175,34.35 ; 30.6,34.175 31,34.175 R701.1@31.175,34.35 ; 30.625,35.125 31,35.125 31.175,34.95 R701.1@31.175,34.7 R701.1@31.175,34.35
  Signal Layer 3 w0.5: v1(28.9,29.05) 28.9,32.787 v1(29.39,33.276) 29.936,33.276 v1(29.962,33.302) ; v1@30,33.25 30.238,33.012 ; v1@30.225,32.45 30.232,32.457 v1@30.244,32.457 ; v1(30.258,32.443) v1@30.244,32.457 ; v1@30.7,32.475 30.7,32.55 30.238,33.012 ; v1@30.85,32.425 30.886,32.461 33.264,32.461 v1(33.275,32.45) ; v1(30.865,32.471) 30.851,32.457 v1@30.244,32.457 ; 30.238,33.012 30.238,32.464 v1@30.244,32.457
  Bottom Layer w0.5: v1(29.39,33.276) 29.391,33.278 29.935,33.278 v1(29.962,33.302) v1(29.962,33.302) 29.962,33.304 29.9,33.366 TP700.1@29.9,34.4
VMCU_S: C700.1 C701.1 R701.2 R710.2 R760.2 TP701.1 TP705.1 U700.3 U702.2 U702.4 U702.9 U702.10 | length 38
  Top Layer w0.1: R701.2@28.325,34.7 29.325,34.7 29.625,35 29.625,35.725 R710.2@29.15,36.2
  Top Layer w0.2: U700.3@24.775,33.925 25.15,33.925 ; 25.3,34.175 25.2,34.075 25.2,33.817 25.317,33.7 25.57,33.7 R760.2@25.573,33.703 ; v1@25.573,34.148 R760.2@25.573,33.703 ; C701.1@26.075,33.725 26.075,33.704 26.074,33.703 R760.2@25.573,33.703 ; C701.1@26.134,33.687 C701.1@26.134,33.69 ; 26.15,34.275 26.134,34.259 26.134,34.225 C701.1@26.134,33.69 ; C700.1@26.9,34.125 26.9,34.118 26.532,33.75 26.194,33.75 C701.1@26.134,33.69 ; U702.10@41.815,36.675 42.5,36.675 v1(42.602,36.777) ; U702.9@41.815,37.075 42.25,37.075 v1@42.475,36.85 ; U702.2@43.585,36.275 43.2,36.275 42.698,36.777 v1(42.602,36.777) ; U702.4@43.585,37.075 43.175,37.075 43,36.9 42.725,36.9 v1(42.602,36.777)
  Top Layer w0.25: U700.3@24.775,33.925 24.75,33.95 U700.3@24.75,34.075 24.75,34.2 24.775,34.225 v1(25.575,34.225)
  Top Layer w0.5: v1@25.504,34.225 26.134,34.225 C700.1@27.033,34.225 C700.1@27.033,34.351 ; v1(25.9,34.725) v1(25.9,34.725) 26.134,34.489 26.134,34.259 ; C700.1@26.968,34.287 C700.1@27.033,34.351 ; 27.075,35.125 27.033,35.083 C700.1@27.033,34.351 ; 27.375,35.2 28.15,35.2 28.325,35.025 R701.2@28.325,34.7 28.325,34.55 28.15,34.375 27.056,34.375 C700.1@27.033,34.351
  Signal Layer 3 w0.6: v1(25.575,34.225) 25.575,34.4 v1(25.9,34.725) v1(27.771,36.596) ; v1@27.775,36.6 42.425,36.6 v1(42.602,36.777)
  Bottom Layer w0.5: v1(27.771,36.596) 27.772,36.594 27.87,36.594 28.465,36 TP701.1@28.6,36 ; TP705.1@41.6,36.2 42.177,36.777 v1(42.602,36.777)
VMCU_SENSE: C632.1 R630.1 R631.2 TP708.1 U910.6 | length 4.9
  Top Layer w0.1: v1(49.575,34.1) 49.65,34.025 U910.6@50.625,34.025 50.65,34 51.05,34 C632.1@51.05,32.775 51.075,32.8 R631.2@51.6,32.8 R630.1@52.15,32.8
  Bottom Layer w0.1: TP708.1@48.8,34.8 49.5,34.1 v1(49.575,34.1)
VTARGET: R629.2 R691.1 U800.1 U806.1 | length 29.7
  Top Layer w0.3: R691.1@63.477,26.187 63.476,26.186 63.476,26.173 R629.2@64.409,26.173 ; R629.2@64.419,26.163 R629.2@64.409,26.173 ; v1(64.477,26.652) 64.439,26.614 64.439,26.173 R629.2@64.409,26.173 ; U806.1@72.35,34.85 72.45,34.85 72.575,34.975 72.575,35.269 72.518,35.325 v1(72.518,35.382) ; U800.1@72.35,43.85 72.35,44.375 v1(72.475,44.5)
  Signal Layer 3 w0.3: v1(64.477,26.652) 64.929,26.2 67.836,26.2 68.329,25.707 70.457,25.707 v1(70.55,25.8)
  Signal Layer 4 w0.3: v1(70.55,25.8) 70.55,26.325 72.25,28.025 72.25,28.769 72.45,28.969 v1(72.45,29.025) 72.025,29.45 72.025,34.832 72.518,35.325 v1(72.518,35.382) ; v1(72.475,44.5) 73.025,43.95 73.025,40.1 72.593,39.668 v1@72.593,35.343
VTARGET_BUF: C655.1 C806.1 L801.1 R636.2 R687.2 R801.2 R809.2 U808.23 U808.24 | length 80.3
  Top Layer w0.2: v1(63.731,47.322) 63.731,47.274 64.155,46.85 C806.1@64.175,46.85 ; R801.2@67.849,42.793 68.266,42.793 68.523,43.05 v1(68.525,43.05)
  Top Layer w0.3: R687.2@29.656,22.903 29.688,22.935 30.454,22.935 C655.1@30.59,23.071 ; C655.1@30.604,23.036 30.712,22.928 30.712,22.225 v1(30.752,22.186) ; R636.2@47.2,32.8 47.2,33.625 v1(47.35,33.775) ; L801.1@54.7,37.3 L801.1@54.709,37.309 ; R809.2@54.925,38.125 54.925,37.525 L801.1@54.709,37.309 ; v1(55.575,37.312) 55.572,37.309 L801.1@54.709,37.309 ; C806.1@64.15,46.825 U808.24@64.15,45.845 64.78,45.845 65.195,45.43 U808.23@65.195,45.3 ; v1@68.45,43.05 v1@68.523,43.05
  Signal Layer 3 w0.3: v1(30.752,22.186) 47.789,22.186 47.838,22.235 47.985,22.235 v1(48.025,22.275)
  Signal Layer 3 w0.4: v1(47.35,33.775) 47.366,33.791 47.366,34.166 47.85,34.65 53.625,34.65 55.575,36.6 ; v1(60.625,35.45) 57.438,35.45 56.138,36.75 ; 55.575,36.6 55.575,36.784 v1(55.575,37.312) 56.138,36.75 ; 55.575,36.6 55.759,36.784 56.091,36.784 56.125,36.75 56.138,36.75
  Signal Layer 4 w0.3: v1@47.3,33.725 47.344,33.725 47.39,33.679 47.39,33.079 48.7,31.769 48.7,28.55 48.025,27.875 48.025,22.371 48.046,22.35 v1@48.075,22.35
  Signal Layer 4 w0.4: v1(60.625,35.45) 60.625,37.046 60.904,37.325 60.904,38.546 59.525,39.925 59.525,40.825 60.55,41.85 61.05,41.85 61.7,42.5 61.7,45.29 v1(63.731,47.322) 63.731,47.731 64.525,48.525 67.6,48.525 68.182,47.943 68.182,46.285 68.525,45.942 68.525,44.284 68.793,44.016 68.793,43.293 v1@68.5,43
VTARGET_SENSE: C638.1 R636.1 R637.2 U910.5 | length 3.2
  Top Layer w0.1: C638.1@46.1,32.775 46.125,32.8 R637.2@46.65,32.8 ; U910.5@46.225,34.025 U910.5@46.65,34.025 ; U910.5@46.775,34.025 U910.5@46.65,34.025 ; R636.1@47.2,32.2 47.2,32.25 R637.2@46.65,32.8 ; R637.2@46.65,32.8 U910.5@46.65,34.025
VTREF: Q800.4 R816.2 TPJ817.1 U800.2 | length 52.4
  Top Layer w0.3: Q800.4@67.325,36.65 67.325,35.725 v1(67.45,35.6) ; U800.2@71.9,44.8 71.9,45.65 R816.2@71.95,45.7 72.025,45.775 v1(72.025,46.55)
  Signal Layer 3 w0.3: v1(65.689,45.981) 65.745,45.981 65.89,46.125 68.45,46.125 68.575,46 71,46 71.55,46.55 v1(72.025,46.55) 72.275,46.3 100.575,46.3 v1(101.475,47.2)
  Signal Layer 4 w0.3: v1(65.689,45.981) 65.689,45.924 65.475,45.71 65.475,40.6 67.175,38.9 67.175,37.825 67.45,37.55 v1(67.45,35.6)
  Bottom Layer w0.5: v1(101.475,47.2) 101.477,47.202 101.502,47.202 TPJ817.1@102.65,48.35
pads on no net: D1.1 D1.3 D800.5 D801.1 J101.5 J101.7 J101.9 J101.11 J101.13 M2.1 M3.1 P100.11 P100.12 P101.M1 P101.M2 P103.4 P601.25@1.8,56.82 P601.26@1.8,48.18 P601.27@6.2,56.525 P601.27@6.85,56.82 P601.28@6.2,48.475 P601.28@6.85,48.18 P601.A2 P601.A3 P601.A8 P601.A10 P601.A11 P601.B2 P601.B3 P601.B8 P601.B10 P601.B11 P601.M1 P601.M2 P800.7 P800.11 P800.13 P801.10 P801.12 P801.14 P801.16 P801.18 P801.20 P801.M1 P801.M2 Q100.3 RP800.2 RP800.7 SW105.7 SW105.8 SW105.M1 SW105.M2 U600.8 U701.8 U704.1 U704.5 U704.8 U705.1 U705.5 U705.8 U800.17 U802.17 U806.17 U808.8 U808.9 U808.10 U810.17 U900.B11 U900.E12 U900.F12 U900.G2 U900.H2 U900.J2 U900.L3 U900.L8 U900.L12 U900.M4 U900.M12 U900.M13 U900.N7 U900.N12 U901.9 U902.C1

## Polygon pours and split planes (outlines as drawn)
GND on Top Layer "GND_L01_P021" (solid, remove dead copper, pour order 21): 0,0 0,60 125,60 125,0
5V on Top Layer "5V_L01_P019" (solid, remove dead copper, pour order 19): 10.6,53.525 10.6,55.075 11.075,55.55 11.925,55.55 12.275,55.2 12.275,53.65 12.25,53.65 12.125,53.525 10.675,53.525
5V on Top Layer "5V_L01_P018" (solid, remove dead copper, pour order 18): 14.375,54.625 13.975,55.025 13.975,56.175 14.325,56.525 16.375,56.525 16.8,56.1 16.8,55.225 16.45,54.875 15.725,54.875 15.725,54.7 15.65,54.625
3V3 on Top Layer "3V3_L01_P017" (solid, remove dead copper, pour order 17): 17.025,54.5 16.825,54.3 16.825,53.85 16.225,53.25 16.225,51.875 16.55,51.55 17.95,51.55 18.25,51.85 18.25,52.55 17.775,53.025 17.775,54.2 17.475,54.5
5V on Top Layer "5V_L01_P013" (solid, remove dead copper, pour order 13): 31.7,33.075 31.7,33.625 32.15,34.075 32.15,34.35 32.25,34.45 33.25,34.45 33.725,34.925 34.05,34.925 34.325,34.65 34.325,33.4 33.825,32.9 32.25,32.9 32.075,33.075
USBC_VBUS on Top Layer "USBC_VBUS_L01_P020" (solid, remove dead copper, pour order 20): 9.85,55.125 9.85,53.575 8.825,53.575 8.4,54 8.4,54.725 9,55.325 9.717,55.325
VMCU_R on Top Layer "VMCU_R_L01_P016" (solid, remove dead copper, pour order 16): 31.5,32.2 31.475,32.225 31.475,32.8 31.375,32.9 31.05,32.9 30.25,33.7 29.3,33.7 28.95,33.35 28.95,32.575 29.35,32.175 31.475,32.175 31.5,32.2 31.5,32.225
VMCU_R on Top Layer "VMCU_R_L01_P015" (solid, remove dead copper, pour order 15): 30.525,35.475 30.375,35.325 30.375,34.25 29.875,33.75 29.325,33.75 28.95,33.375 28.95,33.2 29.175,32.975 30.125,32.975 31.05,33.9 31.475,33.9 31.575,34 31.575,35.475
VMCU_S on Top Layer "VMCU_S_L01_P014" (solid, remove dead copper, pour order 14): 28.725,35.5 28.675,35.45 28.675,33.925 27.25,33.925 27.15,33.825 26.75,33.825 26.475,33.55 26.45,33.575 25.275,33.575 25.075,33.775 25.075,34.95 25.6,35.475 28.575,35.475 28.6,35.5
AEM_VMCU on Top Layer "AEM_VMCU_L01_P002" (solid, remove dead copper, pour order 2): 24.375,32.875 24.35,32.9 23.65,32.9 23.3,32.55 23.3,31.625 23.1,31.425 23.1,31 23.325,30.775 24.3,30.775 24.55,31.025 24.55,31.5 24.375,31.675
3V3 on VCC Layer 5 "3V3_L05_P024" (solid, remove dead copper, pour order 24): 16.15,52.715 15.7,52.265 15.7,47.925 18.175,45.45 18.25,45.458 36.067,45.458 36.4,45.125 37.6,43.95 42.725,43.95 44.575,42.1 44.575,35.575 41.525,32.525 41.2,32.525 33.6,32.525 30.15,35.975 17.65,35.975 11.95,35.975 11.325,35.35 11.325,32.222 11.661,31.886 17.463,26.038 17.463,7.025 17.663,6.825 28.225,6.825 28.775,7.375 28.775,23.225 29.55,24 76.575,24 77.05,24.475 77.1,24.525 77.1,39.675 77.25,39.825 77.8,40.375 101.225,40.375 101.9,40.375 102.2,40.675 102.2,59.2 101.925,59.475 99.625,59.475 99.2,59.05 99.2,53.975 95.575,50.35 77.5,50.35 70.55,57.3 70.358,57.3 70.356,57.299 68.151,57.301 63.565,52.715
5V on VCC Layer 5 "5V_L05_P005" (solid, remove dead copper, pour order 5): 67.725,57.55 63.35,53.175 16.125,53.175 15.875,52.925 15.35,52.4 15.35,47.925 18.05,45.225 35.988,45.225 37.487,43.7 42.575,43.7 44.275,42 44.275,35.65 41.4,32.775 33.7,32.775 30.275,36.2 8.05,36.2 7.65,36.6 7.65,59.275 7.825,59.45 98.45,59.45 99,58.9 99,54.1 98.912,53.987 95.5,50.575 77.75,50.575 70.775,57.55 68.35,57.55
GND on VCC Layer 5 "VCC Layer 5-GND" (solid, remove dead copper, pour order 28): 16.925,0.733 16.692,0.5 0.5,0.5 0.5,59.05 0.95,59.5 7.1,59.5 7.1,36.175 7.437,35.838 10.25,35.849 10.825,35.274 10.825,32.125 16.925,26.025
VMCU on VCC Layer 5 "VMCU_L05_P027" (solid, remove dead copper, pour order 27): 17.4,1.05 18.459,-0.009 19.244,-0.009 20.575,-0.009 114.525,-0.009 114.525,59.991 103.25,59.991 102.45,59.175 102.45,40.575 101.991,40.116 101.25,40.116 78.05,40.116 77.525,39.575 77.375,39.425 77.375,24.4 76.691,23.716 29.575,23.716 29.075,23.216 29.075,7.066 28.55,6.541 17.625,6.541 17.4,6.316
GND on Signal Layer 3 "GND_L03_P025" (solid, remove dead copper, pour order 25): 0,0 0,60 125,60 125,0
3V3 on Signal Layer 3 "3V3_L03_P022" (solid, remove dead copper, pour order 22): 18.15,51.675 18.525,52.05 18.525,54.175 17.7,55 17.7,56.85 17.225,57.325 16.3,57.325 15.925,56.95 15.925,55.125 16.525,54.525 16.525,51.775 16.625,51.675
GND on GND Layer 2 "GND_L02_P009" (solid, remove dead copper, pour order 9): 0,0 0,60 125,60 125,0
GND on Bottom Layer "GND_L06_P008" (solid, remove dead copper, pour order 8): 0,0 0,60 125,60 125,0
GND on Signal Layer 4 "GND_L04_P012" (solid, remove dead copper, pour order 12): 0.328,0.844 0.328,60.844 125.328,60.844 125.328,0.844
